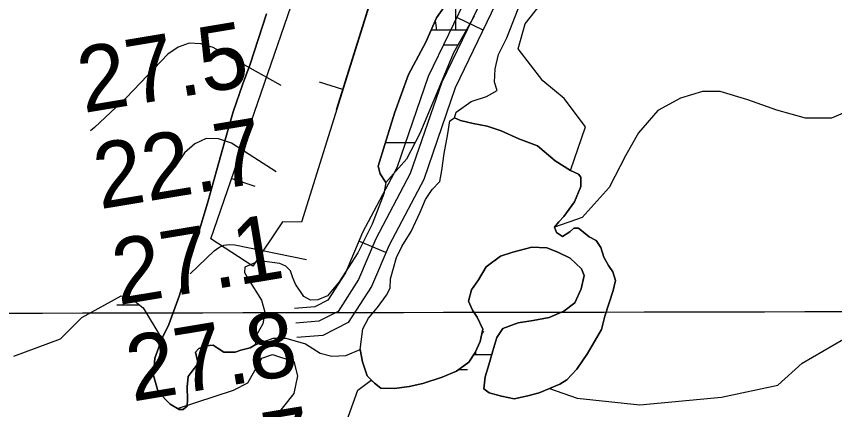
# Model space of a CAD drawing. Extents: x 3297772 to 3335630, y 634068 to 659439.
# Drawn here: x 3328275 to 3329113, y 648465 to 648868 of the extents above; entities that cross this region are included whole.
import ezdxf

# ---------------------------------------------------------------- set-up
doc = ezdxf.new("R2010")
doc.units = 0
for name, color, linetype in [('V-BORW-LINE', 7, 'Continuous'), ('V-GRID-MAJR', 7, 'Continuous'), ('V-RIVR-RANG', 7, 'Continuous'), ('V-ROAD-CNTR', 7, 'Continuous'), ('V-SITE-VEGE', 7, 'Continuous'), ('V-TOPO-MAJR', 7, 'Continuous'), ('V-TOPO-MINR', 7, 'Continuous'), ('V-TOPO-SHOR', 7, 'Continuous'), ('V-WETL-SWMP', 7, 'Continuous')]:
    doc.layers.add(name, color=color, linetype=linetype)

msp = doc.modelspace()

# ---------------------------------------------------------------- linework, layer by layer
at = {"layer": 'V-BORW-LINE'}
for p, q in [((3328609.275, 648792.6199999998), (3328585.412, 648800.0729999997)), ((3328495.435, 648701.6479999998), (3328519.073, 648693.5109999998))]:
    msp.add_line(p, q, dxfattribs=at)
for points in [[(3328718.15, 649171.6599999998), (3328710.282, 649116.0339999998), (3328566.821, 648656.6849999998), (3328547.474, 648657.2149999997), (3328517.058, 648611.7109999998), (3328474.143, 648639.7979999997), (3328666.303, 649198.0049999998), (3328718.15, 649171.6599999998)], [(3328602.862, 648772.0839999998), (3328710.282, 649116.0339999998), (3328718.15, 649171.6599999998)]]:
    msp.add_lwpolyline(points, dxfattribs=at)
at = {"layer": 'V-GRID-MAJR'}
msp.add_spline([(3301875.511, 648538.54), (3307136.054, 648541.983), (3312396.597, 648546.191), (3317657.139, 648551.165), (3322917.681, 648556.903), (3328178.222, 648563.407), (3333438.761, 648570.676), (3333438.762, 648570.676)], degree=3, dxfattribs=at)
at = {"layer": 'V-ROAD-CNTR'}
for p, q in [((3328752.969456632, 648853.6252660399), (3328725.95051067, 648866.662239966)), ((3328653.474655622, 648625.721721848), (3328625.8447108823, 648637.409698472))]:
    msp.add_line(p, q, dxfattribs=at)
for points in [[(3329123.9147147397, 649311.3633505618), (3329107.311747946, 649288.1623969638), (3329046.9718686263, 649245.735481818), (3328992.986976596, 649212.9195474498), (3328938.0200865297, 649174.2286248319), (3328915.7721310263, 649153.787665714), (3328885.239192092, 649100.952771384), (3328821.46531964, 649003.7099658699), (3328791.8543788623, 648951.553070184), (3328766.0464304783, 648880.7262118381), (3328724.473513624, 648794.569384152), (3328692.1955781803, 648700.4915723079), (3328656.656649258, 648633.244706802), (3328638.706685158, 648590.8107916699), (3328614.803732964, 648553.74086581), (3328588.9617846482, 648540.583892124), (3328562.3328379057, 648538.3798965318)], [(3328738.374485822, 648892.4101884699), (3328696.6775692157, 648805.997361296), (3328664.5776334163, 648712.4395484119), (3328629.53070351, 648646.1206810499), (3328612.088738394, 648604.8887635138), (3328593.9777746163, 648576.8028196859), (3328580.6078013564, 648569.9958332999), (3328559.858842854, 648568.277836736)], [(3328752.21045815, 648886.5682001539), (3328710.57554142, 648800.2833727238), (3328678.386605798, 648706.46556036), (3328643.093676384, 648639.6826939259), (3328625.3977117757, 648597.849777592), (3328604.39075379, 648565.2718427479), (3328584.784793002, 648555.2898627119), (3328561.0958403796, 648553.3288666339)]]:
    msp.add_lwpolyline(points, dxfattribs=at)
at = {"layer": 'V-SITE-VEGE'}
for points in [[(3328610.2600000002, 648444.5970000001), (3328624.832, 648484.685), (3328638.451, 648494.911), (3328641.607, 648491.581), (3328648.201, 648486.524), (3328662.181, 648486.121), (3328677.326, 648488.433), (3328691.308, 648491.5210000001), (3328711.1180000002, 648497.712), (3328725.88, 648503.907), (3328738.315, 648513.211), (3328744.928, 648523.3), (3328749.989, 648534.554), (3328752.721, 648546.977), (3328746.913, 648559.406), (3328742.258, 648566.402), (3328738, 648575.727), (3328741.119, 648587.37), (3328748.119, 648597.458), (3328756.291, 648611.0380000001), (3328770.67, 648621.893), (3328783.486, 648626.15), (3328802.907, 648631.174), (3328818.437, 648630.38), (3328829.6950000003, 648626.095), (3328842.11, 648619.8690000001), (3328853.747, 648608.984), (3328856.4560000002, 648601.99), (3328853.333, 648588.408), (3328847.105, 648574.045), (3328835.835, 648565.517), (3328820.684, 648558.933), (3328804.3740000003, 648555.8470000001), (3328788.8370000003, 648553.535), (3328773.301, 648547.728), (3328767.077, 648538.416), (3328762.791, 648524.832), (3328758.892, 648510.469), (3328754.994, 648498.0480000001), (3328753.815, 648486.014), (3328759.2460000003, 648481.736), (3328771.667, 648478.228), (3328784.864, 648475.493), (3328798.846, 648478.584), (3328810.4990000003, 648481.676), (3328820.989, 648486.323), (3328831.477, 648490.583), (3328838.86, 648495.234), (3328848.969, 648506.095), (3328859.858, 648522.001), (3328874.253, 648546.833), (3328877.7660000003, 648560.42), (3328886.3370000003, 648586.8150000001), (3328888.68, 648596.907), (3328885.97, 648605.84), (3328881.319, 648612.4450000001), (3328876.668, 648620.9940000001), (3328873.573, 648630.703), (3328868.9220000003, 648638.086), (3328861.5500000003, 648641.59), (3328856.12, 648646.256), (3328850.6890000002, 648650.534), (3328846.0300000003, 648650.5380000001), (3328841.754, 648646.661), (3328834.3710000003, 648642.01), (3328828.163, 648646.286), (3328826.228, 648651.728), (3328830.504, 648657.157), (3328835.558, 648662.589), (3328846.45, 648677.7170000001), (3328853.069, 648693.243), (3328853.079, 648702.948), (3328850.753, 648706.057), (3328842.6040000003, 648709.561), (3328857.949, 648754.368), (3328836.093, 648783.5210000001), (3328814.239, 648801.7440000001), (3328788.741, 648834.5430000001), (3328796.028, 648860.055), (3328821.524, 648892.853)], [(3328530.998, 648870.284), (3328514.242, 648818.662), (3328506.84, 648798.481), (3328497.102, 648769.758), (3328488.914, 648741.035), (3328479.946, 648709.207), (3328471.3710000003, 648678.542), (3328462.403, 648649.0430000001), (3328453.83, 648621.096), (3328441.744, 648580.73), (3328431.228, 648552.009), (3328423.8370000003, 648537.265), (3328416.822, 648517.469), (3328415.245, 648499.611), (3328420.275, 648482.907), (3328432.2970000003, 648470.081), (3328439.842, 648465.667)], [(3328439.842, 648465.667), (3328497.342, 648484.685), (3328511.913, 648491.974), (3328526.485, 648517.486), (3328537.411, 648521.129), (3328559.267, 648513.84), (3328562.9080000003, 648499.263), (3328559.267, 648481.041), (3328530.126, 648444.5970000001)]]:
    msp.add_lwpolyline(points, dxfattribs=at)
at = {"layer": 'V-TOPO-MAJR'}
for points in [[(3328541.0026769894, 648708.3908570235), (3328495.2616285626, 648737.7339666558), (3328481.807409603, 648742.1159487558), (3328469.1637332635, 648742.5734717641), (3328457.735870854, 648737.1443061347), (3328447.1185510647, 648727.7906814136), (3328437.31578058, 648713.2467997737)], [(3328452.856242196, 648603.8305117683), (3328477.5690628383, 648627.4746508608), (3328482.3601589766, 648630.8399897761), (3328487.452957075, 648633.1571044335), (3328492.9983081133, 648633.901882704), (3328498.845361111, 648633.5984367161), (3328572.043573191, 648618.5463493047)]]:
    msp.add_lwpolyline(points, dxfattribs=at)
at = {"layer": 'V-TOPO-MINR'}
msp.add_lwpolyline([(3328546.056765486, 648796.794710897), (3328476.3352563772, 648835.7546721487), (3328463.923470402, 648839.5570307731), (3328451.986490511, 648840.1939782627), (3328440.761719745, 648836.0828090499), (3328430.0117550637, 648828.8062287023), (3328387.6706338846, 648784.5644775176), (3328354.810068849, 648753.7469082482), (3328350.8392124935, 648750.521778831)], dxfattribs=at)
at = {"layer": 'V-TOPO-SHOR'}
for points in [[(3328717.389, 648883.66), (3328705.332, 648866.201), (3328694.433, 648841.363), (3328676.531, 648807.99), (3328662.12, 648768.403), (3328645.361, 648714.063), (3328647.681, 648706.295), (3328653.495, 648697.357), (3328651.15, 648685.71), (3328639.467, 648654.6630000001), (3328624.678, 648625.169), (3328605.617, 648595.682), (3328593.565, 648581.33), (3328583.8510000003, 648577.0700000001), (3328576.085, 648576.691), (3328569.491, 648580.582), (3328560.963, 648593.0160000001), (3328558.251, 648599.621), (3328555.542, 648607.002), (3328550.889, 648611.665)], [(3328550.889, 648611.665), (3328544.679, 648614.3910000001), (3328524.103, 648617.133), (3328508.954, 648610.551), (3328508.558, 648605.113), (3328512.8200000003, 648598.12), (3328525.997, 648576.7490000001), (3328529.4790000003, 648564.319), (3328527.523, 648552.674), (3328521.2970000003, 648541.421), (3328519.343, 648530.941), (3328514.293, 648527.838), (3328504.97, 648525.52), (3328499.146, 648523.587), (3328487.497, 648523.599), (3328480.511, 648527.877), (3328476.632, 648530.601), (3328468.866, 648529.833), (3328461.8740000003, 648527.1240000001), (3328458.3740000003, 648523.634), (3328459.5330000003, 648518.973), (3328461.08, 648511.981), (3328456.023, 648505.386), (3328450.969, 648498.402), (3328449.791, 648487.921), (3328450.166, 648475.106), (3328449.769, 648468.1190000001), (3328445.881, 648464.629), (3328441.609, 648464.633), (3328432.2970000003, 648470.081), (3328420.275, 648482.907), (3328415.247, 648499.611), (3328416.822, 648517.469), (3328423.835, 648537.263), (3328431.228, 648552.009), (3328441.744, 648580.73), (3328453.83, 648621.096), (3328462.403, 648649.0430000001), (3328471.369, 648678.542), (3328479.946, 648709.207), (3328488.914, 648741.035), (3328497.102, 648769.758), (3328506.84, 648798.481), (3328514.242, 648818.662), (3328530.998, 648870.284)], [(3328658.04, 648598.728), (3328664.276, 648620.463), (3328669.728, 648631.719), (3328679.452, 648647.2390000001), (3328688.406, 648667.031), (3328693.855, 648679.837), (3328700.857, 648690.312), (3328708.632, 648698.457), (3328710.5870000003, 648709.715), (3328712.937, 648727.184), (3328716.842, 648747.372), (3328718.8000000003, 648760.571), (3328723.85, 648763.672), (3328729.673, 648760.948), (3328742.87, 648757.8250000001), (3328757.235, 648755.091), (3328771.595, 648750.415), (3328789.446, 648742.2390000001), (3328808.853, 648734.84), (3328826.6950000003, 648719.677), (3328842.6040000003, 648709.561), (3328850.753, 648706.057), (3328853.079, 648702.948), (3328853.069, 648693.243), (3328846.45, 648677.7170000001), (3328835.558, 648662.589), (3328830.504, 648657.157), (3328826.228, 648651.728), (3328828.163, 648646.2880000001), (3328834.3710000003, 648642.01), (3328841.754, 648646.661), (3328846.0300000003, 648650.5380000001), (3328850.6890000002, 648650.534), (3328856.12, 648646.256), (3328861.5500000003, 648641.59), (3328868.9220000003, 648638.086), (3328873.573, 648630.703), (3328876.668, 648620.9940000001), (3328881.319, 648612.4450000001), (3328885.97, 648605.84), (3328888.677, 648596.905), (3328886.3370000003, 648586.8150000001), (3328877.764, 648560.42), (3328874.253, 648546.833), (3328859.858, 648522.001), (3328848.969, 648506.095), (3328838.86, 648495.234), (3328831.477, 648490.583), (3328820.989, 648486.323), (3328810.4990000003, 648481.676), (3328798.846, 648478.584), (3328784.864, 648475.493), (3328771.667, 648478.228), (3328759.2460000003, 648481.736), (3328753.815, 648486.014), (3328754.994, 648498.0480000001), (3328758.892, 648510.469), (3328762.791, 648524.832), (3328767.077, 648538.416), (3328773.301, 648547.728), (3328788.84, 648553.535), (3328804.3740000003, 648555.8470000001), (3328820.684, 648558.933), (3328835.835, 648565.517), (3328847.105, 648574.045), (3328853.333, 648588.406), (3328856.4560000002, 648601.99), (3328853.747, 648608.984), (3328842.11, 648619.8690000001), (3328829.693, 648626.095), (3328818.437, 648630.38), (3328802.907, 648631.174), (3328783.486, 648626.15), (3328770.67, 648621.893), (3328756.291, 648611.0380000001), (3328748.119, 648597.458), (3328741.119, 648587.37), (3328738, 648575.727), (3328742.2600000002, 648566.402), (3328746.911, 648559.406), (3328752.721, 648546.977), (3328749.989, 648534.554), (3328744.928, 648523.3), (3328738.315, 648513.211), (3328725.88, 648503.907), (3328711.1180000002, 648497.712), (3328691.308, 648491.5210000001), (3328677.326, 648488.433), (3328662.181, 648486.121), (3328648.201, 648486.524), (3328641.607, 648491.581), (3328634.238, 648499.355), (3328629.595, 648513.726), (3328626.894, 648526.155), (3328629.636, 648547.507), (3328635.473, 648558.372), (3328644.804, 648569.232), (3328654.136, 648582.037), (3328657.6410000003, 648589.02), (3328658.04, 648598.728)]]:
    msp.add_lwpolyline(points, dxfattribs=at)
at = {"layer": 'V-WETL-SWMP'}
for p, q in [((3328725.164366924, 648853.8737917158), (3328725.164366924, 648889.5283746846)), ((3328699.922721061, 648853.8737917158), (3328735.917825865, 648853.8737917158)), ((3328713.164366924, 648838.4427917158), (3328727.321678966, 648838.4427917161)), ((3328652.8786634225, 648738.4417917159), (3328683.335923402, 648738.4417917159)), ((3328770.6694922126, 648621.8939034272), (3328783.487490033, 648626.1508994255)), ((3328783.487490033, 648626.1508994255), (3328802.9074870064, 648631.1758938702)), ((3328802.9074870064, 648631.1758938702), (3328818.438485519, 648630.3808911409)), ((3328818.438485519, 648630.3808911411), (3328829.693485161, 648626.0968904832)), ((3328829.693485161, 648626.0968904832), (3328842.111485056, 648619.8698902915)), ((3328756.290495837, 648611.0389100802), (3328770.6694922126, 648621.8939034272)), ((3328842.111485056, 648619.8698902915), (3328853.7474859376, 648608.9848919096)), ((3328748.1204993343, 648597.4589164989), (3328756.290495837, 648611.0389100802)), ((3328853.7474859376, 648608.9848919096), (3328856.456487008, 648601.9918938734)), ((3328856.456487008, 648601.9918938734), (3328853.3344899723, 648588.4058993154)), ((3328741.1195020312, 648587.370921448), (3328748.1204993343, 648597.4589164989)), ((3328737.9995046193, 648575.7269261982), (3328741.1195020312, 648587.370921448)), ((3328853.334489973, 648588.4058993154), (3328847.105493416, 648574.0469056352)), ((3328341.9960201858, 648558.9320370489), (3328382.2990626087, 648581.3781149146)), ((3328382.2990626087, 648581.3781149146), (3328393.280011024, 648578.2260202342)), ((3328393.280011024, 648578.2260202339), (3328404.777164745, 648568.7983023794)), ((3328742.2605059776, 648566.4029286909), (3328737.9995046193, 648575.7269261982)), ((3328847.105493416, 648574.0469056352), (3328835.835496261, 648565.5179108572)), ((3328377.8492140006, 648571.942615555), (3328400.9426575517, 648571.942615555)), ((3328404.7771647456, 648568.7983023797), (3328423.8351512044, 648537.2651129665)), ((3328746.911506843, 648559.407930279), (3328742.2605059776, 648566.4029286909)), ((3328835.835496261, 648565.5179108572), (3328820.684499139, 648558.9339161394)), ((3328320.0009246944, 648536.9878617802), (3328341.9960201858, 648558.9320370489)), ((3328752.7215086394, 648546.9769335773), (3328746.911506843, 648559.407930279)), ((3328820.684499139, 648558.9339161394), (3328804.373501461, 648555.8469204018)), ((3328788.839503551, 648553.5349242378), (3328773.301506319, 648547.728929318)), ((3328804.373501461, 648555.8469204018), (3328788.839503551, 648553.5349242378)), ((3328749.9885113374, 648534.5549385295), (3328752.7215086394, 648546.9769335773)), ((3328773.301506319, 648547.728929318), (3328767.0775087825, 648538.4179338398)), ((3329079.9435114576, 648512.1761033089), (3329132.8117040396, 648542.9774567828)), ((3328272.3795248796, 648519.2571279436), (3328320.0009246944, 648536.9878617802)), ((3328423.8351512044, 648537.2651129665), (3328416.8231557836, 648517.4711213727)), ((3328519.345142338, 648530.9420966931), (3328537.9825331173, 648537.7659785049)), ((3328537.9825331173, 648537.7659785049), (3328551.059327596, 648537.7506012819)), ((3328551.059327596, 648537.7506012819), (3328570.929765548, 648531.9725696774)), ((3328570.929765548, 648531.9725696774), (3328586.0874598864, 648522.5390086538)), ((3328744.9285140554, 648523.2999435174), (3328749.9885113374, 648534.5549385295)), ((3328767.0775087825, 648538.4179338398), (3328762.7905118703, 648524.8329395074)), ((3328458.3761501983, 648523.6351111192), (3328461.875149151, 648527.1251091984)), ((3328459.535150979, 648518.9741125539), (3328458.3761501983, 648523.6351111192)), ((3328461.875149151, 648527.1251091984), (3328468.867147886, 648529.8351068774)), ((3328468.867147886, 648529.8351068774), (3328476.633146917, 648530.6031050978)), ((3328476.633146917, 648530.603105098), (3328480.513147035, 648527.8801053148)), ((3328480.513147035, 648527.8801053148), (3328487.497147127, 648523.6011054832)), ((3328487.497147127, 648523.6011054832), (3328499.146145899, 648523.5881032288)), ((3328499.146145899, 648523.5881032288), (3328504.972144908, 648525.5221014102)), ((3328504.972144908, 648525.5221014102), (3328514.294143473, 648527.8410987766)), ((3328514.294143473, 648527.8410987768), (3328519.345142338, 648530.9420966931)), ((3328612.238814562, 648519.8936596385), (3328626.8935259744, 648526.1549653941)), ((3328626.8935259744, 648526.1549653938), (3328629.596528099, 648513.7269692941)), ((3328762.7905118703, 648524.8329395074), (3328758.891515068, 648510.4709453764)), ((3328416.8231557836, 648517.4711213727), (3328415.2491594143, 648499.6121280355)), ((3328461.0801521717, 648511.983114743), (3328459.535150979, 648518.9741125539)), ((3328586.0874598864, 648522.5390086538), (3328598.115357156, 648519.3858200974)), ((3328598.115357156, 648519.3858200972), (3328612.238814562, 648519.8936596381)), ((3328738.3155167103, 648513.2129483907), (3328744.9285140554, 648523.2999435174)), ((3328743.552208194, 648521.2006245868), (3328761.804410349, 648521.2006245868)), ((3328456.0251539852, 648505.3881180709), (3328461.080152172, 648511.9831147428)), ((3328629.596528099, 648513.7269692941), (3328634.2395303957, 648499.3549735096)), ((3328725.879519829, 648503.9079541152), (3328738.3155167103, 648513.2129483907)), ((3328758.8915150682, 648510.4709453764), (3328754.9945178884, 648498.0499505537)), ((3329054.8094167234, 648489.7129294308), (3329079.9435114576, 648512.1761033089)), ((3328415.2491594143, 648499.6121280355), (3328420.277162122, 648482.910133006)), ((3328449.792158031, 648487.9231254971), (3328450.9691558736, 648498.4051215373)), ((3328450.9691558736, 648498.4051215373), (3328456.0251539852, 648505.3881180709)), ((3328634.2395303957, 648499.3549735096), (3328641.607531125, 648491.580974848)), ((3328711.117522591, 648497.7129591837), (3328725.879519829, 648503.9079541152)), ((3328728.3676204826, 648505.7696273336), (3328737.1652078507, 648505.7696273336)), ((3328641.607531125, 648491.580974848), (3328648.2025314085, 648486.5259753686)), ((3328677.326527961, 648488.4329690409), (3328691.308525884, 648491.522965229)), ((3328691.308525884, 648491.522965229), (3328711.117522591, 648497.7129591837)), ((3328754.9945178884, 648498.0499505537), (3328753.8155203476, 648486.0149550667)), ((3328420.277162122, 648482.910133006), (3328432.2991633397, 648470.082135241)), ((3328450.166160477, 648475.109129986), (3328449.792158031, 648487.9231254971)), ((3328648.2025314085, 648486.5259753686), (3328662.18053001, 648486.1209728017)), ((3328662.18053001, 648486.1209728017), (3328677.326527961, 648488.4329690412)), ((3328753.8155203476, 648486.0149550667), (3328759.246520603, 648481.7369555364)), ((3328759.246520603, 648481.7369555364), (3328771.667519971, 648478.2279543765)), ((3328798.84751703, 648478.5849489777), (3328810.4995151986, 648481.6779456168)), ((3328810.4995151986, 648481.6779456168), (3328820.9885131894, 648486.3249419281)), ((3328820.9885131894, 648486.3249419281), (3328849.2225938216, 648476.3522544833)), ((3328997.256475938, 648477.2260381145), (3329054.8094167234, 648489.7129294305)), ((3328449.769161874, 648468.1211325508), (3328450.166160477, 648475.109129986)), ((3328771.667519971, 648478.2279543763), (3328784.865519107, 648475.4949527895)), ((3328784.865519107, 648475.4949527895), (3328798.84751703, 648478.5849489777)), ((3328849.2225938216, 648476.3522544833), (3328913.5534862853, 648469.4770571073)), ((3328913.5534862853, 648469.4770571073), (3328997.256475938, 648477.2260381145)), ((3328432.2991633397, 648470.082135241), (3328441.611163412, 648464.6351353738)), ((3328445.8821629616, 648464.6311345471), (3328449.769161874, 648468.1211325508)), ((3328441.611163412, 648464.635135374), (3328445.8821629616, 648464.6311345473))]:
    msp.add_line(p, q, dxfattribs=at)
for points in [[(3328743.664, 648867.779), (3328722.697, 648830.1410000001), (3328705.911, 648789.883), (3328688.077, 648747.533), (3328674.446, 648721.395), (3328653.495, 648697.357), (3328647.681, 648706.294), (3328645.36, 648714.063), (3328662.119, 648768.403), (3328676.532, 648807.991), (3328694.432, 648841.362), (3328705.332, 648866.2000000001), (3328717.389, 648883.659)], [(3329135.529, 648774.178), (3329109.8850000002, 648763.223), (3329083.208, 648763.254), (3329053.9250000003, 648771.657), (3329024.122, 648782.153), (3328995.8850000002, 648790.555), (3328977.577, 648790.577), (3328955.077, 648783.803), (3328932.0470000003, 648771.275), (3328912.143, 648748.283), (3328899.039, 648725.283), (3328882.262, 648692.348), (3328854.503, 648661.518), (3328826.228, 648651.727), (3328830.505, 648657.158), (3328835.559, 648662.588), (3328846.449, 648677.718), (3328853.068, 648693.242), (3328853.079, 648702.949), (3328850.753, 648706.058), (3328842.603, 648709.562), (3328826.6950000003, 648719.676), (3328808.852, 648734.84), (3328789.446, 648742.24), (3328771.595, 648750.414), (3328757.234, 648755.09), (3328742.87, 648757.8250000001), (3328729.6720000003, 648760.947), (3328723.8510000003, 648763.671), (3328725.427, 648769.4230000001), (3328740.609, 648780.39), (3328756.308, 648785.603), (3328767.3000000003, 648791.867), (3328764.694, 648800.2390000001), (3328765.233, 648813.839), (3328768.911, 648828.481), (3328777.301, 648845.733), (3328788.843, 648875.535)]]:
    msp.add_lwpolyline(points, dxfattribs=at)
for centre, radius, start, end in [((3328669.9214308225, 648854.3485948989), 35.24628790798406, 359.2281799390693, 14.599016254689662), ((3328780.408138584, 648521.6754276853), 35.246287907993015, 139.2281768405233, 144.72608590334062), ((3328780.408138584, 648521.6754276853), 35.246287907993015, 176.23822610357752, 180.77183517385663)]:
    msp.add_arc(centre, radius, start, end, dxfattribs=at)

# ---------------------------------------------------------------- texts
at = {"layer": 'V-RIVR-RANG'}
for s, p in [('27.5', (3328343.804464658, 648768.5107286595)), ('22.7', (3328360.435464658, 648669.9037286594)), ('27.1', (3328379.408410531, 648571.6846249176)), ('27.8', (3328393.697464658, 648472.6887286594)), ('28.7', (3328410.328464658, 648374.0817286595))]:
    msp.add_text(s, height=67.00000000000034, rotation=9.428325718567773, dxfattribs=at).set_placement(p)

doc.saveas('drawing.dxf')
